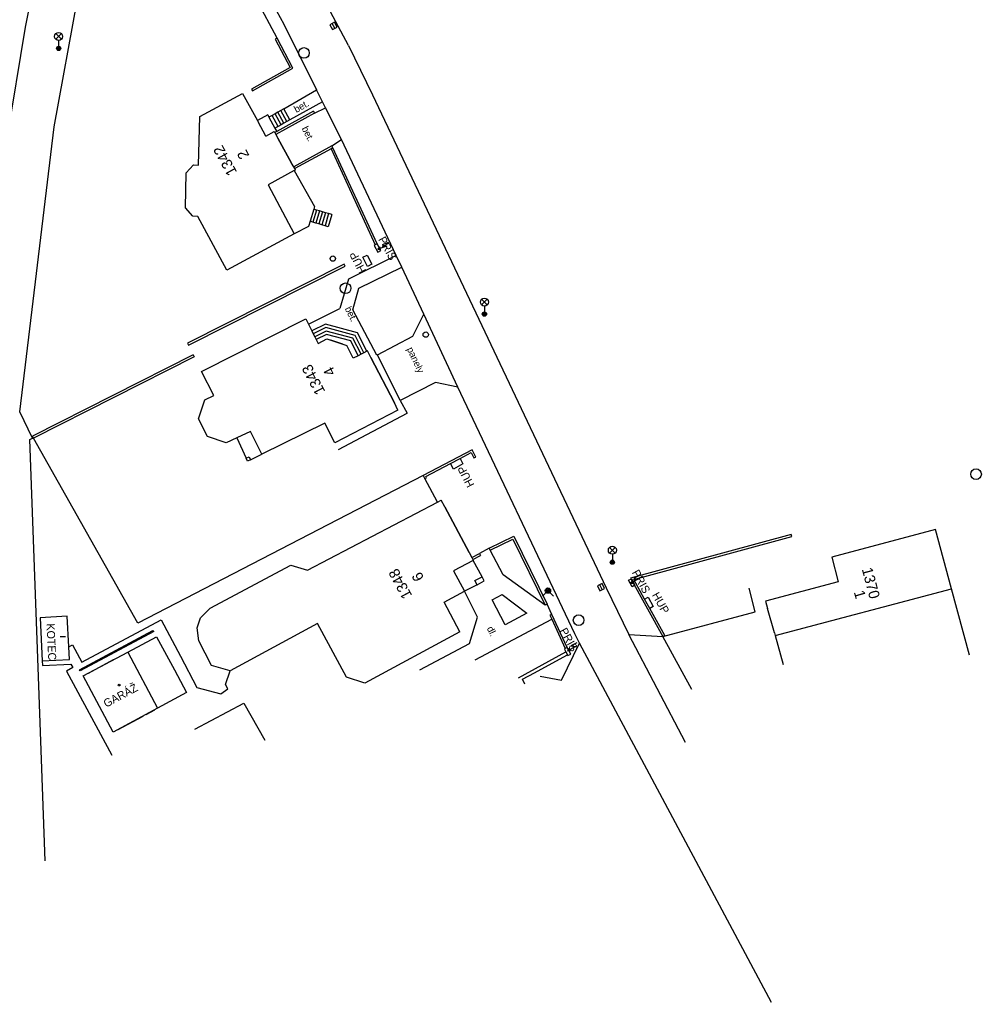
# Model space of a CAD drawing. Extents: x -539694 to -539148, y -1156467 to -1155920.
# Drawn here: x -539618.6 to -539528.4, y -1156467.2 to -1156375.1 of the extents above; entities that cross this region are included whole.
import ezdxf

# ---------------------------------------------------------------- set-up
doc = ezdxf.new("R2010")
doc.units = 0
for name, color, linetype in [('Vrstva 10', 7, 'Continuous'), ('Vrstva 11', 7, 'Continuous'), ('Vrstva 24', 7, 'Continuous'), ('Vrstva 27', 7, 'Continuous'), ('Vrstva 28', 7, 'Continuous'), ('Vrstva 31', 7, 'Continuous'), ('Vrstva 33', 7, 'Continuous'), ('Vrstva 39', 7, 'Continuous'), ('Vrstva 40', 7, 'Continuous'), ('Vrstva 41', 7, 'Continuous'), ('Vrstva 46', 7, 'Continuous'), ('Vrstva 47', 7, 'Continuous'), ('Vrstva 5', 7, 'Continuous'), ('Vrstva 6', 7, 'Continuous'), ('Vrstva 7', 7, 'Continuous'), ('Vrstva 8', 7, 'Continuous')]:
    doc.layers.add(name, color=color, linetype=linetype)

msp = doc.modelspace()

# ---------------------------------------------------------------- linework, layer by layer
at = {"layer": 'Vrstva 10'}
for p, q in [((-539618.035, -1156375.756), (-539615.942, -1156365.397)), ((-539587.76, -1156377.46), (-539593.876, -1156366.013)), ((-539598.33, -1156367.22), (-539593.821, -1156375.467)), ((-539619.735, -1156386.187), (-539618.035, -1156375.756)), ((-539593.821, -1156375.467), (-539590.74, -1156381.63)), ((-539587.76, -1156377.46), (-539585.52, -1156382.09)), ((-539590.19, -1156382.77), (-539590.74, -1156381.63)), ((-539585.52, -1156382.09), (-539563.61, -1156428.31)), ((-539583.28, -1156397.17), (-539588.41, -1156386.3)), ((-539577.52, -1156409.49), (-539580.71, -1156402.65)), ((-539566.54, -1156432.61), (-539577.52, -1156409.49)), ((-539563.61, -1156428.31), (-539561.48, -1156432.7)), ((-539566.11, -1156433.49), (-539566.54, -1156432.61)), ((-539556.18, -1156442.82), (-539561.48, -1156432.7)), ((-539548.12, -1156467.17), (-539566.11, -1156433.49))]:
    msp.add_line(p, q, dxfattribs=at)
for points in [[(-539588.41, -1156386.3), (-539589.918, -1156383.31), (-539590.19, -1156382.77)], [(-539580.71, -1156402.65), (-539582.76, -1156398.26), (-539583.28, -1156397.17)]]:
    msp.add_lwpolyline(points, dxfattribs=at)
at = {"layer": 'Vrstva 11'}
for p, q in [((-539593.531, -1156384.6), (-539594.101, -1156383.57)), ((-539590.93, -1156383.82), (-539589.918, -1156383.31)), ((-539595.32, -1156383.98), (-539596.298, -1156384.516)), ((-539594.352, -1156385.054), (-539594.922, -1156384.024)), ((-539594.073, -1156384.9), (-539594.643, -1156383.87)), ((-539593.802, -1156384.75), (-539594.372, -1156383.72)), ((-539589.31, -1156386.88), (-539588.41, -1156386.3)), ((-539590.747, -1156392.897), (-539591.085, -1156394.032)), ((-539590.469, -1156392.98), (-539590.807, -1156394.115)), ((-539590.192, -1156393.063), (-539590.53, -1156394.198)), ((-539589.905, -1156393.148), (-539590.243, -1156394.283)), ((-539589.617, -1156393.234), (-539589.955, -1156394.369)), ((-539589.33, -1156393.32), (-539589.65, -1156394.46)), ((-539583.28, -1156397.17), (-539587.77, -1156399.39)), ((-539587.77, -1156399.39), (-539588.56, -1156402.13)), ((-539591.506, -1156403.584), (-539588.56, -1156402.13)), ((-539588.704, -1156415.356), (-539582.27, -1156411.95)), ((-539573.27, -1156427.1), (-539574.492, -1156424.79)), ((-539569.33, -1156429.928), (-539573.27, -1156427.1)), ((-539549.65, -1156430.56), (-539550.21, -1156428.35)), ((-539558.29, -1156432.89), (-539549.65, -1156430.56)), ((-539612.75, -1156435.29), (-539605.3, -1156431.3)), ((-539575.898, -1156435.076), (-539568.714, -1156431.247)), ((-539612.96, -1156435.99), (-539606.08, -1156432.3)), ((-539606.01, -1156432.41), (-539612.9, -1156436.1)), ((-539606.08, -1156432.3), (-539606.01, -1156432.41)), ((-539561.48, -1156432.7), (-539558.29, -1156432.89)), ((-539555.58, -1156437.83), (-539558.29, -1156432.89)), ((-539581.068, -1156436.012), (-539576.41, -1156433.53)), ((-539614.19, -1156436.12), (-539609.95, -1156444.01)), ((-539612.9, -1156436.1), (-539612.96, -1156435.99))]:
    msp.add_line(p, q, dxfattribs=at)
for points in [[(-539590.19, -1156382.77), (-539593.26, -1156384.45), (-539593.83, -1156383.42), (-539590.74, -1156381.63)], [(-539593.83, -1156383.42), (-539594.101, -1156383.57), (-539594.372, -1156383.72), (-539594.643, -1156383.87), (-539594.922, -1156384.024), (-539595.212, -1156384.177)], [(-539595.32, -1156383.98), (-539595.212, -1156384.177), (-539594.646, -1156385.21), (-539594.471, -1156385.529)], [(-539593.26, -1156384.45), (-539593.531, -1156384.6), (-539593.802, -1156384.75), (-539594.073, -1156384.9), (-539594.352, -1156385.054), (-539594.646, -1156385.21)], [(-539592.838, -1156389.183), (-539590.94, -1156392.56), (-539591.017, -1156392.818), (-539591.355, -1156393.952), (-539591.5, -1156394.44), (-539592.84, -1156395.14)], [(-539589.33, -1156393.32), (-539589.617, -1156393.234), (-539589.905, -1156393.148), (-539590.192, -1156393.063), (-539590.469, -1156392.98), (-539590.747, -1156392.897), (-539591.017, -1156392.818)], [(-539589.65, -1156394.46), (-539589.955, -1156394.369), (-539590.243, -1156394.283), (-539590.53, -1156394.198), (-539590.807, -1156394.115), (-539591.085, -1156394.032), (-539591.355, -1156393.952)], [(-539587.36, -1156402.24), (-539586.79, -1156400.23), (-539582.76, -1156398.26)], [(-539582.9, -1156410.76), (-539585.03, -1156406.47), (-539585.108, -1156406.511), (-539587.36, -1156402.24)], [(-539585.03, -1156406.47), (-539581.73, -1156404.73), (-539580.71, -1156402.65)], [(-539586.049, -1156406.137), (-539586.92, -1156404.41), (-539589.9, -1156403.6), (-539591.185, -1156404.234)], [(-539586.315, -1156406.275), (-539587.128, -1156404.664), (-539589.869, -1156403.919), (-539591.052, -1156404.503)], [(-539586.581, -1156406.414), (-539587.335, -1156404.919), (-539589.838, -1156404.239), (-539590.92, -1156404.772)], [(-539586.847, -1156406.553), (-539587.543, -1156405.173), (-539589.807, -1156404.558), (-539590.787, -1156405.041)], [(-539577.52, -1156409.49), (-539579.61, -1156409.05), (-539582.9, -1156410.76), (-539582.27, -1156411.95)], [(-539576.41, -1156433.53), (-539575.66, -1156431.07), (-539576.89, -1156428.64)], [(-539574.28, -1156429.44), (-539573.36, -1156428.94), (-539571.03, -1156430.68), (-539573.06, -1156431.79), (-539574.28, -1156429.44)], [(-539605.3, -1156431.3), (-539603.5, -1156434.73), (-539601.96, -1156437.66), (-539599.71, -1156438.24)], [(-539613.97, -1156433.83), (-539613.61, -1156433.66), (-539612.75, -1156435.29)], [(-539569.8, -1156436.59), (-539567.81, -1156436.96), (-539566.11, -1156433.49)], [(-539616.46, -1156435.15), (-539616.44, -1156435.6), (-539613.78, -1156435.47)], [(-539613.78, -1156435.47), (-539613.6, -1156435.79), (-539614.19, -1156436.12)], [(-539599.71, -1156438.24), (-539599.06, -1156437.78), (-539599.29, -1156437.36), (-539598.84, -1156436.1)]]:
    msp.add_lwpolyline(points, dxfattribs=at)
at = {"layer": 'Vrstva 24'}
for p, q in [((-539584.17, -1156396.27), (-539584.994, -1156396.564)), ((-539584.8, -1156396.378), (-539584.994, -1156396.564)), ((-539584.018, -1156395.95), (-539584.607, -1156396.16)), ((-539584.607, -1156396.16), (-539584.17, -1156396.27)), ((-539584.994, -1156396.564), (-539584.726, -1156396.585)), ((-539560.562, -1156427.455), (-539561.322, -1156427.889)), ((-539561.164, -1156427.672), (-539561.322, -1156427.889)), ((-539560.468, -1156427.113), (-539561.012, -1156427.424)), ((-539561.012, -1156427.424), (-539560.562, -1156427.455)), ((-539561.322, -1156427.889), (-539561.055, -1156427.863)), ((-539566.46, -1156433.799), (-539567.227, -1156434.221)), ((-539567.065, -1156434.007), (-539567.227, -1156434.221)), ((-539567.227, -1156434.221), (-539566.959, -1156434.199)), ((-539566.361, -1156433.459), (-539566.909, -1156433.761)), ((-539566.909, -1156433.761), (-539566.46, -1156433.799))]:
    msp.add_line(p, q, dxfattribs=at)
for points in [[(-539584.735, -1156396.69), (-539585.072, -1156396.076), (-539585.248, -1156396.173), (-539585.335, -1156396.221), (-539584.998, -1156396.835), (-539584.735, -1156396.69)], [(-539586.01, -1156397.12), (-539585.57, -1156397.97), (-539585.969, -1156398.176), (-539586.409, -1156397.326), (-539586.01, -1156397.12)], [(-539577.297, -1156416.191), (-539577.03, -1156416.7), (-539577.91, -1156417.19), (-539578.189, -1156416.658)], [(-539561.173, -1156428.219), (-539561.51, -1156427.605), (-539561.247, -1156427.46), (-539560.91, -1156428.074), (-539561.173, -1156428.219)], [(-539560.003, -1156429.378), (-539559.68, -1156429.2), (-539559.2, -1156430.06), (-539559.526, -1156430.241)], [(-539566.927, -1156434.519), (-539567.264, -1156433.905), (-539567.44, -1156434.002), (-539567.527, -1156434.05), (-539567.38, -1156434.318), (-539567.236, -1156434.581), (-539567.19, -1156434.664), (-539566.927, -1156434.519)]]:
    msp.add_lwpolyline(points, dxfattribs=at)
at = {"layer": 'Vrstva 27'}
for p, q in [((-539589.043, -1156375.861), (-539589.277, -1156375.419)), ((-539563.991, -1156428.475), (-539564.209, -1156428.025))]:
    msp.add_line(p, q, dxfattribs=at)
for points in [[(-539588.822, -1156375.744), (-539589.056, -1156375.302), (-539589.498, -1156375.536), (-539589.264, -1156375.978)], [(-539563.766, -1156428.366), (-539563.984, -1156427.916), (-539564.434, -1156428.134), (-539564.216, -1156428.584)]]:
    msp.add_lwpolyline(points, close=True, dxfattribs=at)
for centre in [(-539591.93, -1156378.17), (-539588.03, -1156400.23), (-539528.95, -1156417.66), (-539566.19, -1156431.34)]:
    msp.add_circle(centre, 0.5, dxfattribs=at)
at = {"layer": 'Vrstva 28'}
for centre in [(-539589.22, -1156397.45), (-539580.52, -1156404.58)]:
    msp.add_circle(centre, 0.25, dxfattribs=at)
at = {"layer": 'Vrstva 31'}
msp.add_lwpolyline([(-539569.59, -1156429.1), (-539569.06, -1156428.57), (-539568.53, -1156429.1)], dxfattribs=at)
for radius in [0.25, 0.18, 0.11]:
    msp.add_circle((-539569.06, -1156428.57), radius, dxfattribs=at)
at = {"layer": 'Vrstva 33'}
for p, q in [((-539615.185, -1156376.89), (-539614.655, -1156376.36)), ((-539615.185, -1156376.36), (-539614.655, -1156376.89)), ((-539614.92, -1156377), (-539614.92, -1156377.75)), ((-539575.285, -1156401.79), (-539574.755, -1156401.26)), ((-539575.285, -1156401.26), (-539574.755, -1156401.79)), ((-539575.02, -1156401.9), (-539575.02, -1156402.65)), ((-539563.295, -1156425.05), (-539562.765, -1156424.52)), ((-539563.295, -1156424.52), (-539562.765, -1156425.05)), ((-539563.03, -1156425.16), (-539563.03, -1156425.91))]:
    msp.add_line(p, q, dxfattribs=at)
for centre, radius in [((-539614.92, -1156376.625), 0.375), ((-539614.92, -1156377.75), 0.2), ((-539614.92, -1156377.75), 0.145), ((-539614.92, -1156377.75), 0.0876), ((-539575.02, -1156401.525), 0.375), ((-539575.02, -1156402.65), 0.2), ((-539575.02, -1156402.65), 0.145), ((-539575.02, -1156402.65), 0.0876), ((-539563.03, -1156424.785), 0.375), ((-539563.03, -1156425.91), 0.2), ((-539563.03, -1156425.91), 0.145), ((-539563.03, -1156425.91), 0.0876)]:
    msp.add_circle(centre, radius, dxfattribs=at)
at = {"layer": 'Vrstva 39'}
msp.add_line((-539614.78, -1156432.87), (-539614.28, -1156432.87), dxfattribs=at)
for radius in [0.09, 0.0398]:
    msp.add_circle((-539609.246, -1156437.425), radius, dxfattribs=at)
at = {"layer": 'Vrstva 5'}
for p, q in [((-539601.68, -1156384.14), (-539597.7, -1156381.96)), ((-539601.82, -1156388.69), (-539601.68, -1156384.14)), ((-539595.5, -1156385.96), (-539596.23, -1156384.64)), ((-539595.5, -1156385.96), (-539594.707, -1156385.522)), ((-539594.363, -1156386.152), (-539593.084, -1156388.489)), ((-539602.97, -1156389.42), (-539602.27, -1156388.65)), ((-539602.27, -1156388.65), (-539601.82, -1156388.69)), ((-539603.02, -1156392.68), (-539602.97, -1156389.42)), ((-539595.27, -1156390.55), (-539592.84, -1156395.14)), ((-539602.33, -1156393.47), (-539603.02, -1156392.68)), ((-539601.882, -1156393.494), (-539602.33, -1156393.47)), ((-539599.15, -1156398.55), (-539601.882, -1156393.494)), ((-539592.84, -1156395.14), (-539599.15, -1156398.55)), ((-539601.52, -1156408.03), (-539591.75, -1156403.09)), ((-539590.613, -1156405.394), (-539589.779, -1156404.983)), ((-539589.779, -1156404.983), (-539587.921, -1156405.607)), ((-539587.303, -1156406.791), (-539587.921, -1156405.607)), ((-539585.67, -1156406.72), (-539585.96, -1156406.09)), ((-539585.67, -1156406.72), (-539583.46, -1156410.96)), ((-539600.382, -1156410.281), (-539601.52, -1156408.03)), ((-539601.21, -1156410.7), (-539600.382, -1156410.281)), ((-539601.8, -1156412.47), (-539601.21, -1156410.7)), ((-539583.12, -1156411.65), (-539583.46, -1156410.96)), ((-539583.12, -1156411.65), (-539589.046, -1156414.716)), ((-539600.97, -1156414.12), (-539601.8, -1156412.47)), ((-539589.96, -1156412.862), (-539595.88, -1156415.78)), ((-539589.046, -1156414.716), (-539589.96, -1156412.862)), ((-539595.88, -1156415.78), (-539596.93, -1156413.65)), ((-539599.21, -1156414.71), (-539600.97, -1156414.12)), ((-539598.228, -1156414.254), (-539597.34, -1156416.164)), ((-539596.937, -1156416.301), (-539595.88, -1156415.78)), ((-539597.34, -1156416.164), (-539597.07, -1156416.031)), ((-539597.207, -1156416.434), (-539597.34, -1156416.164)), ((-539596.937, -1156416.301), (-539597.207, -1156416.434)), ((-539597.07, -1156416.031), (-539596.937, -1156416.301)), ((-539578.74, -1156420.73), (-539579.07, -1156420.09)), ((-539578.74, -1156420.73), (-539576.44, -1156425.01)), ((-539532.737, -1156422.859), (-539542.471, -1156425.435)), ((-539531.236, -1156428.421), (-539532.737, -1156422.859)), ((-539576.06, -1156425.75), (-539577.906, -1156426.734)), ((-539575.238, -1156427.271), (-539576.06, -1156425.75)), ((-539542.471, -1156425.435), (-539541.857, -1156427.755)), ((-539600.71, -1156430.22), (-539593.15, -1156426.19)), ((-539593.15, -1156426.19), (-539591.59, -1156426.65)), ((-539577.906, -1156426.734), (-539576.89, -1156428.64)), ((-539575.903, -1156427.618), (-539575.238, -1156427.271)), ((-539575.695, -1156428.017), (-539575.903, -1156427.618)), ((-539575.695, -1156428.017), (-539575.03, -1156427.67)), ((-539575.03, -1156427.67), (-539575.238, -1156427.271)), ((-539541.857, -1156427.755), (-539548.692, -1156429.564)), ((-539578.79, -1156429.653), (-539576.89, -1156428.64)), ((-539575.695, -1156428.017), (-539576.89, -1156428.64)), ((-539547.759, -1156432.794), (-539531.236, -1156428.421)), ((-539529.558, -1156434.639), (-539531.236, -1156428.421)), ((-539577.31, -1156432.43), (-539578.79, -1156429.653)), ((-539548.692, -1156429.564), (-539548.49, -1156430.26)), ((-539601.63, -1156431.13), (-539600.71, -1156430.22)), ((-539547.83, -1156432.53), (-539548.49, -1156430.26)), ((-539614.11, -1156430.98), (-539616.66, -1156431.11)), ((-539616.66, -1156431.11), (-539616.46, -1156435.15)), ((-539613.97, -1156433.83), (-539614.11, -1156430.98)), ((-539601.95, -1156432.06), (-539601.63, -1156431.13)), ((-539601.79, -1156433.27), (-539601.95, -1156432.06)), ((-539590.66, -1156431.66), (-539598.84, -1156436.1)), ((-539587.93, -1156436.7), (-539590.66, -1156431.66)), ((-539577.31, -1156432.43), (-539586.23, -1156437.26)), ((-539608.45, -1156434.34), (-539605.75, -1156432.9)), ((-539605.75, -1156432.9), (-539604.07, -1156435.99)), ((-539600.59, -1156435.59), (-539601.79, -1156433.27)), ((-539613.91, -1156435.04), (-539613.97, -1156433.83)), ((-539616.46, -1156435.15), (-539613.91, -1156435.04)), ((-539612.61, -1156436.57), (-539608.45, -1156434.34)), ((-539608.45, -1156434.34), (-539605.65, -1156439.6)), ((-539604.07, -1156435.99), (-539602.93, -1156438.14)), ((-539598.84, -1156436.1), (-539600.59, -1156435.59)), ((-539609.8, -1156441.84), (-539612.61, -1156436.57)), ((-539586.23, -1156437.26), (-539587.93, -1156436.7)), ((-539602.93, -1156438.14), (-539605.65, -1156439.6)), ((-539605.65, -1156439.6), (-539609.8, -1156441.84)), ((-539602.17, -1156441.55), (-539597.56, -1156439.12)), ((-539597.56, -1156439.12), (-539595.59, -1156442.6))]:
    msp.add_line(p, q, dxfattribs=at)
for points in [[(-539597.7, -1156381.96), (-539596.298, -1156384.516), (-539596.23, -1156384.64)], [(-539594.707, -1156385.522), (-539594.65, -1156385.627), (-539594.554, -1156385.802), (-539594.363, -1156386.152)], [(-539592.736, -1156389.126), (-539592.838, -1156389.183), (-539595.27, -1156390.55)], [(-539592.736, -1156389.126), (-539592.797, -1156389.014), (-539592.893, -1156388.839), (-539593.084, -1156388.489)], [(-539591.75, -1156403.09), (-539591.506, -1156403.584), (-539591.185, -1156404.234), (-539591.052, -1156404.503), (-539590.92, -1156404.772), (-539590.787, -1156405.041), (-539590.613, -1156405.394)], [(-539585.96, -1156406.09), (-539586.049, -1156406.137), (-539586.315, -1156406.275), (-539586.581, -1156406.414), (-539586.847, -1156406.553), (-539587.303, -1156406.791)], [(-539596.93, -1156413.65), (-539598.228, -1156414.254), (-539599.21, -1156414.71)], [(-539591.59, -1156426.65), (-539579.416, -1156420.275), (-539579.07, -1156420.09)], [(-539576.44, -1156425.01), (-539576.205, -1156425.467), (-539576.114, -1156425.645), (-539576.06, -1156425.75)], [(-539547.83, -1156432.53), (-539547.759, -1156432.794), (-539547.03, -1156435.5)]]:
    msp.add_lwpolyline(points, dxfattribs=at)
at = {"layer": 'Vrstva 6'}
for p, q in [((-539593.084, -1156388.489), (-539594.363, -1156386.152)), ((-539588.3, -1156405.48), (-539589.4, -1156405.11)), ((-539583.46, -1156410.96), (-539585.67, -1156406.72)), ((-539576.44, -1156425.01), (-539578.74, -1156420.73)), ((-539609.82, -1156435.07), (-539612.16, -1156436.33)), ((-539606.71, -1156440.18), (-539605.9, -1156439.74)), ((-539609.34, -1156441.59), (-539607, -1156440.33))]:
    msp.add_line(p, q, dxfattribs=at)
at = {"layer": 'Vrstva 7'}
for p, q in [((-539615.34, -1156385.09), (-539610.03, -1156356.24)), ((-539618.55, -1156411.81), (-539615.34, -1156385.09)), ((-539589.39, -1156387.151), (-539585.248, -1156396.173)), ((-539585.072, -1156396.076), (-539589.214, -1156387.055)), ((-539602.763, -1156405.571), (-539588.08, -1156398.148)), ((-539588.08, -1156398.148), (-539588.17, -1156397.97)), ((-539602.303, -1156406.482), (-539617.36, -1156414.094)), ((-539617.363, -1156414.276), (-539618.55, -1156411.81)), ((-539617.63, -1156414.42), (-539617.363, -1156414.276)), ((-539616.94, -1156433.19), (-539617.63, -1156414.42)), ((-539617.363, -1156414.276), (-539617.27, -1156414.272)), ((-539617.27, -1156414.272), (-539617.36, -1156414.094)), ((-539607.51, -1156431.64), (-539617.27, -1156414.272)), ((-539576.16, -1156415.37), (-539580.765, -1156417.782)), ((-539580.765, -1156417.782), (-539607.51, -1156431.64)), ((-539574.492, -1156424.79), (-539572.342, -1156423.738)), ((-539572.342, -1156423.738), (-539569.33, -1156429.928)), ((-539572.25, -1156423.47), (-539569.15, -1156429.84)), ((-539561.022, -1156427.536), (-539546.207, -1156423.505)), ((-539576.114, -1156425.645), (-539575.399, -1156425.278)), ((-539569.15, -1156429.84), (-539569.33, -1156429.928)), ((-539616.19, -1156453.91), (-539616.94, -1156433.19)), ((-539571.83, -1156436.76), (-539567.38, -1156434.318))]:
    msp.add_line(p, q, dxfattribs=at)
for points in [[(-539596.857, -1156381.555), (-539596.76, -1156381.73), (-539592.96, -1156379.61), (-539594.44, -1156376.8), (-539594.617, -1156376.893)], [(-539594.617, -1156376.893), (-539593.228, -1156379.53), (-539596.857, -1156381.555)], [(-539591.026, -1156383.645), (-539594.471, -1156385.529), (-539594.65, -1156385.627)], [(-539591.026, -1156383.645), (-539590.93, -1156383.82), (-539594.554, -1156385.802)], [(-539589.214, -1156387.055), (-539589.31, -1156386.88), (-539592.893, -1156388.839)], [(-539589.214, -1156387.055), (-539589.39, -1156387.151), (-539592.797, -1156389.014)], [(-539588.17, -1156397.97), (-539602.853, -1156405.393), (-539602.763, -1156405.571)], [(-539602.303, -1156406.482), (-539602.213, -1156406.66), (-539617.27, -1156414.272)], [(-539580.432, -1156417.987), (-539580.495, -1156417.866), (-539578.189, -1156416.658), (-539577.297, -1156416.191), (-539576.248, -1156415.642), (-539575.999, -1156416.139)], [(-539575.999, -1156416.139), (-539575.82, -1156416.05), (-539576.16, -1156415.37)], [(-539580.765, -1156417.782), (-539580.609, -1156418.08), (-539580.59, -1156418.07), (-539580.432, -1156417.987)], [(-539574.492, -1156424.79), (-539574.58, -1156424.61), (-539572.25, -1156423.47)], [(-539546.207, -1156423.505), (-539546.26, -1156423.312), (-539561.32, -1156427.41)], [(-539576.205, -1156425.467), (-539575.49, -1156425.1), (-539575.399, -1156425.278)], [(-539561.32, -1156427.41), (-539558.29, -1156432.89), (-539558.115, -1156432.793)], [(-539558.115, -1156432.793), (-539559.526, -1156430.241), (-539560.003, -1156429.378), (-539561.022, -1156427.536)], [(-539567.264, -1156433.905), (-539568.7, -1156430.8), (-539568.882, -1156430.884)], [(-539568.882, -1156430.884), (-539568.714, -1156431.247), (-539567.44, -1156434.002)], [(-539571.229, -1156437.332), (-539571.438, -1156436.887), (-539570.317, -1156436.272), (-539570.054, -1156436.127), (-539567.236, -1156434.581)]]:
    msp.add_lwpolyline(points, dxfattribs=at)
at = {"layer": 'Vrstva 8'}
for p, q in [((-539594.44, -1156376.8), (-539596.34, -1156373.23)), ((-539579.416, -1156420.275), (-539580.59, -1156418.07)), ((-539574.58, -1156424.61), (-539575.49, -1156425.1)), ((-539568.7, -1156430.8), (-539569.15, -1156429.84))]:
    msp.add_line(p, q, dxfattribs=at)

# ---------------------------------------------------------------- texts
at = {"layer": 'Vrstva 40'}
for s, rotation, p in [('bet.', 28.68886, (-539592.648, -1156383.802)), ('bet.', 296.75949, (-539592.163, -1156385.249)), ('bet.', 296.40455, (-539588.125, -1156402.138)), ('panely', 295.00314, (-539582.302, -1156405.925)), ('dl.', 295.94715, (-539574.811, -1156432.112))]:
    msp.add_text(s, height=0.65, rotation=rotation, dxfattribs=at).set_placement(p)
at = {"layer": 'Vrstva 41'}
for s, rotation, p in [('PRIS', 298.76062, (-539584.989, -1156395.643)), ('HUP', 117.36821, (-539586.06, -1156398.58)), ('HUP', 117.36821, (-539575.933, -1156418.654)), ('PRIS', 298.76062, (-539561.223, -1156426.869)), ('HUP', 299.16761, (-539559.341, -1156428.983)), ('KOTEC', 272.8341, (-539616.06, -1156431.67)), ('PRIS', 298.76062, (-539567.99, -1156432.32)), ('GARÁŽ', 28.35837, (-539610.463, -1156439.558))]:
    msp.add_text(s, height=0.75, rotation=rotation, dxfattribs=at).set_placement(p)
at = {"layer": 'Vrstva 46'}
for s, rotation, p in [('2', 117.67212, (-539597.021, -1156387.801)), ('4', 116.57015, (-539588.933, -1156408.15)), ('6', 115.64613, (-539580.65, -1156427.412)), ('1', 286.21173, (-539540.412, -1156428.706))]:
    msp.add_text(s, height=1, rotation=rotation, dxfattribs=at).set_placement(p)
at = {"layer": 'Vrstva 47'}
for s, rotation, p in [('1342', 118.69113, (-539598.171, -1156389.342)), ('1343', 117.56273, (-539589.912, -1156409.898)), ('1348', 118.04544, (-539581.767, -1156429.028)), ('1370', 284.82376, (-539539.66, -1156426.55))]:
    msp.add_text(s, height=1, rotation=rotation, dxfattribs=at).set_placement(p)

doc.saveas('drawing.dxf')
